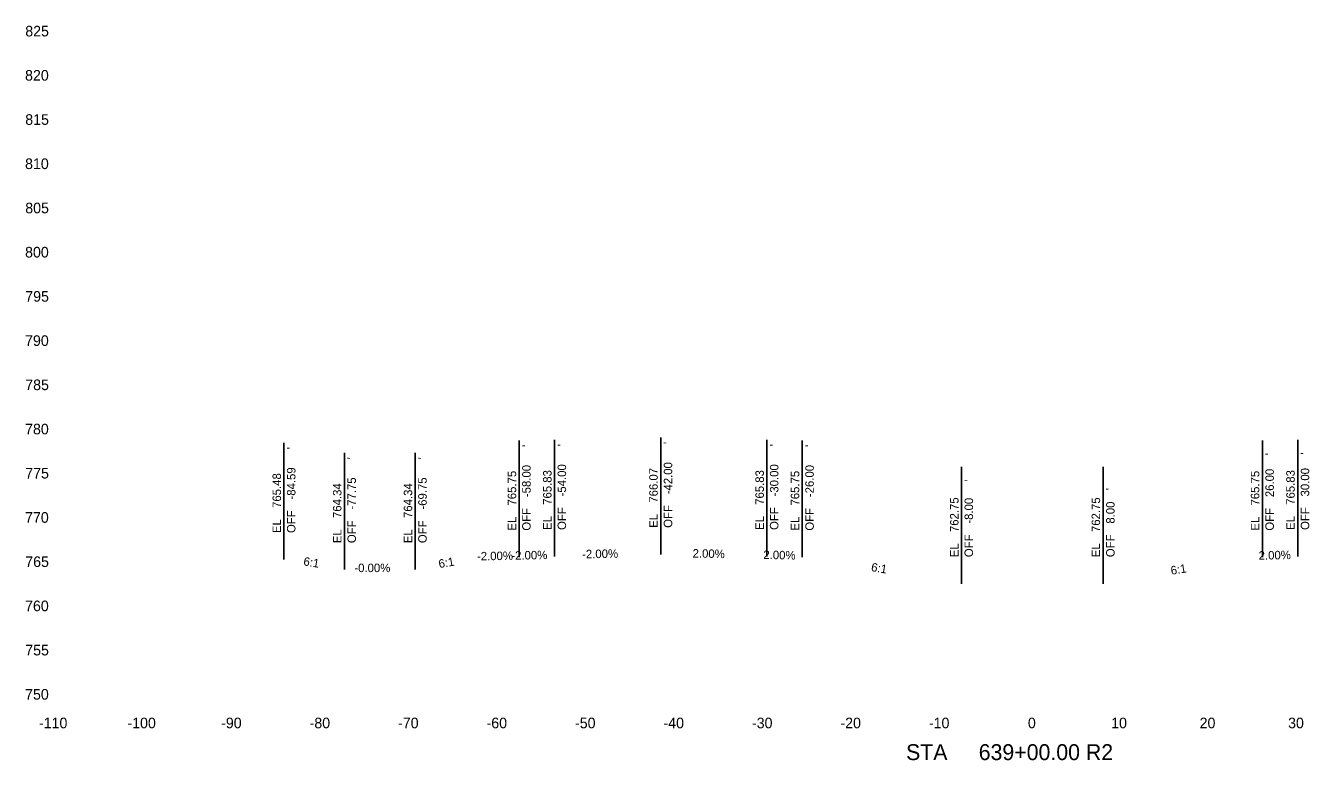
# Model space of a CAD drawing. Extents: x -114 to 173, y 743 to 828.
# Drawn here: x -113.8 to 31.3, y 743.4 to 826.5 of the extents above; entities that cross this region are included whole.
import ezdxf

# ---------------------------------------------------------------- set-up
doc = ezdxf.new("R2010")
doc.units = 0
for name, color, linetype in [('XS-Feature Text', 7, 'Continuous'), ('XS-Segment Text', 7, 'Continuous'), ('XS-Text', 7, 'Continuous')]:
    doc.layers.add(name, color=color, linetype=linetype)

msp = doc.modelspace()

# ---------------------------------------------------------------- linework, layer by layer
at = {"layer": 'XS-Feature Text'}
for p, q in [((-84.59, 766.08), (-84.59, 779.28)), ((-58, 766.35), (-58, 779.55)), ((-54, 766.43), (-54, 779.63)), ((-42, 766.67), (-42, 779.87)), ((-30, 766.43), (-30, 779.63)), ((-26, 766.35), (-26, 779.55)), ((26, 766.35), (26, 779.55)), ((30, 766.43), (30, 779.63)), ((-77.75, 764.94), (-77.75, 778.14)), ((-69.75, 764.94), (-69.75, 778.14)), ((-8, 763.35), (-8, 776.55)), ((8, 763.35), (8, 776.55))]:
    msp.add_line(p, q, dxfattribs=at)

# ---------------------------------------------------------------- texts
for s, p in [("'", (-40.7, 779.14)), ("'", (-83.29, 778.55)), ("'", (-56.7, 778.82)), ("'", (-52.7, 778.9)), ("'", (-28.7, 778.9)), ("'", (-24.7, 778.82)), ("'", (27.3, 777.88)), ("'", (31.3, 777.96)), ('-84.59', (-83.29, 772.87)), ("'", (-76.45, 777.41)), ("'", (-68.45, 777.41)), ('-58.00', (-56.7, 773.14)), ('-54.00', (-52.7, 773.22)), ('766.07', (-42.34, 772.51)), ('-42.00', (-40.7, 773.46)), ('-30.00', (-28.7, 773.22)), ('-26.00', (-24.7, 773.14)), ('26.00', (27.3, 773.14)), ('30.00', (31.3, 773.22)), ('765.48', (-84.92, 771.92)), ('-77.75', (-76.45, 771.73)), ('-69.75', (-68.45, 771.73)), ('765.75', (-58.34, 772.19)), ('765.83', (-54.34, 772.27)), ('765.83', (-30.34, 772.27)), ('765.75', (-26.34, 772.19)), ("'", (-6.7, 774.88)), ('765.75', (25.66, 772.19)), ('765.83', (29.66, 772.27)), ('764.34', (-78.09, 770.78)), ('764.34', (-70.09, 770.78)), ("'", (9.3, 773.93)), ('OFF ', (-52.7, 769.43)), ('OFF ', (-40.7, 769.67)), ('OFF ', (-28.7, 769.43)), ('762.75', (-8.34, 769.19)), ('-8.00', (-6.7, 770.14)), ('762.75', (7.66, 769.19)), ('8.00', (9.3, 770.14)), ('OFF ', (31.3, 769.43)), ('EL ', (-84.92, 769.08)), ('OFF ', (-83.29, 769.08)), ('OFF ', (-76.45, 767.94)), ('OFF ', (-68.45, 767.94)), ('EL ', (-58.34, 769.35)), ('OFF ', (-56.7, 769.35)), ('EL ', (-54.34, 769.43)), ('EL ', (-42.34, 769.67)), ('EL ', (-30.34, 769.43)), ('EL ', (-26.34, 769.35)), ('OFF ', (-24.7, 769.35)), ('EL ', (25.66, 769.35)), ('OFF ', (27.3, 769.35)), ('EL ', (29.66, 769.43)), ('EL ', (-78.09, 767.94)), ('EL ', (-70.09, 767.94)), ('EL ', (-8.34, 766.35)), ('OFF ', (-6.7, 766.35)), ('EL ', (7.66, 766.35)), ('OFF ', (9.3, 766.35))]:
    msp.add_text(s, height=0.96, rotation=90, dxfattribs=at).set_placement(p)
at = {"layer": 'XS-Segment Text'}
for s, rotation, p in [('6:1', 350.5375, (-82.44, 765.44)), ('6:1', 9.4625, (-67.03, 765.11)), ('-2.00%', 1.1458, (-62.76, 765.97)), ('-2.00%', 1.1458, (-58.88, 766.05)), ('-2.00%', 1.1458, (-50.88, 766.21)), ('2.00%', 358.8542, (-38.41, 766.31)), ('2.00%', 358.8542, (-30.41, 766.15)), ('2.00%', 1.1458, (25.59, 766.06)), ('6:1', 350.5377, (-18.27, 764.78)), ('6:1', 9.4623, (15.72, 764.35))]:
    msp.add_text(s, height=0.96, rotation=rotation, dxfattribs=at).set_placement(p)
msp.add_text('-0.00%', height=0.96, dxfattribs=at).set_placement((-76.63, 764.66))
at = {"layer": 'XS-Text'}
for s, height, p in [('825', 1.2, (-113.83, 825.24)), ('820', 1.2, (-113.85, 820.24)), ('815', 1.2, (-113.83, 815.24)), ('810', 1.2, (-113.85, 810.24)), ('805', 1.2, (-113.83, 805.24)), ('800', 1.2, (-113.85, 800.24)), ('795', 1.2, (-113.83, 795.24)), ('790', 1.2, (-113.85, 790.24)), ('785', 1.2, (-113.83, 785.24)), ('780', 1.2, (-113.85, 780.24)), ('775', 1.2, (-113.83, 775.24)), ('770', 1.2, (-113.85, 770.24)), ('765', 1.2, (-113.83, 765.24)), ('760', 1.2, (-113.85, 760.24)), ('755', 1.2, (-113.83, 755.24)), ('750', 1.2, (-113.85, 750.24)), ('-110', 1.2, (-112.28, 747)), ('-100', 1.2, (-102.28, 747)), ('-90', 1.2, (-91.69, 747)), ('-80', 1.2, (-81.69, 747)), ('-70', 1.2, (-71.69, 747)), ('-60', 1.2, (-61.69, 747)), ('-50', 1.2, (-51.69, 747)), ('-40', 1.2, (-41.69, 747)), ('-30', 1.2, (-31.69, 747)), ('-20', 1.2, (-21.69, 747)), ('-10', 1.2, (-11.69, 747)), ('0', 1.2, (-0.5, 747)), ('10', 1.2, (8.91, 747)), ('20', 1.2, (18.91, 747)), ('30', 1.2, (28.91, 747)), (' STA ', 1.8, (-14.94, 743.4)), ('639+00.00 R2', 1.8, (-6.06, 743.4))]:
    msp.add_text(s, height=height, dxfattribs=at).set_placement(p)

doc.saveas('drawing.dxf')
